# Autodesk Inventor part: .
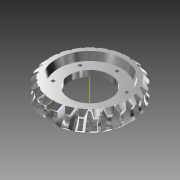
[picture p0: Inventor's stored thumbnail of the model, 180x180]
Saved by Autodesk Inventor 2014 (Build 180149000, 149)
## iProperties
Shininess: 20.0
Length Units: 11269
Angle Units: 11279
Time Units: 11290
Mass Units: 11283
Length Display Precision: 3
Angle Display Precision: 2
Created: 2001-01
Part Number: .
Material: Stainless Steel, 440C
Description: Worm gearing 1/25, 165.
Document SubType Name: Modeling
Density: 7.75 g/cm^3
Appearance: Chrome - Polished
Density: 7.859999999999999
Volumn: 37.595819547659616
Area: 89.95488932430769
PropertySet Name: Model Information
Control State: 0
Master: False
Checked Out: False
ProtocolID: P00020917093351030
Protocol: P00020917093351030<@PID>[Version]<@EL>Version=2.2<@EL>[Main]<@EL>DataFile=SpiData|gear3<@EL>View=MODELB<@EL>Standard=DIN<@EL>PartKey=Gears<@EL>VarLists=A,B,C,D,
Author: PaulN
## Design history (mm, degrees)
sketch "Sketch4"
  geometry: L1 (0, -102.918)-(0, 102.918) reference; L2 (0, 35)-(129.293, 35); L3 (0, 35)-(0, -35); L4 (0, -35)-(129.293, -35); L5 (129.293, 35)-(143.576, 21); L6 (129.293, -35)-(143.576, -21); L7 (-43.64, 0)-(199.773, 0) reference; L8 (107.594, 10)-(70, 10); L9 (107.594, -10)-(70, -10); L10 (107.594, -10)-(114.293, -35); L11 (107.594, 10)-(114.293, 35); L12 (70, 10)-(70, -10); A1 r 30 centre (165, 0) between (143.576, 21) and (143.576, -21); A2 r 73.513 centre (64.646, 0) between (0, 35) and (129.293, 35)
  constraints: 20 end point, 6 point on circle, 5 point on line, 4 perpendicular, 2 centre point, 2 vertical alignment, 1 collinear, 1 equal length, 1 parallel
  dimensions: "d30" = 88.854 deg angle of L6 L5 (= 2 x prf_fi); "d31" = 30 radius of A1 (= prf_a - 0.5 x prf_da2); "d32" = 70 distance of L2.start L3.end (= prf_b2); "d33" = 165 distance from line of L1 A1.centre (= prf_a); "d50" = 44.427 deg angle of L5 L2 (= prf_fi); "d71" = 20 distance between parallel lines of L8 L9; "d74" = 75 deg angle of L2 L11; "d75" = 15 distance of L11.end L2.end; "d76" = 140 diameter of L12 L3
revolve "Revolution3" sketch "Sketch4" stored, may be unused: angle "d35" = 90 deg
workplane "Work Plane4"
sketch "Sketch5"
  geometry: L1 (10, 17.11)-(10, -17.11) reference; L2 (-165.4, 0)-(-92.6, 0) reference; L3 (-155, 12.222)-(-155, -12.222); L4 (-155, -12.222)-(-127, -12.222); L5 (-127, -12.222)-(-103, -3.486); L6 (-103, -3.486)-(-103, 0); L7 (-103, 3.486)-(-127, 12.222); L8 (-127, 12.222)-(-155, 12.222); L9 (-103, 3.486)-(-103, 0); L10 (-115, 0)-(-115, -7.854)
  constraints: 16 end point, 4 perpendicular, 3 equal length, 2 point on line, 1 midpoint, 1 parallel, 1 vertical
  dimensions: "d38" = 165 distance between parallel lines of L1 L3 (= prf_a); "d39" = 20 deg angle of L7 L8 (= prf_alfax); "d40" = 28 distance of L7.end L3.start (= 0.5 x prf_df1); "d41" = 40 distance between parallel lines of L3 L10 (= 0.5 x prf_d1); "d42" = 7.854 distance of L10.start L10.end (= 0.25 x prf_px)
revolve "Revolution4" sketch "Sketch5" stored, may be unused: angle "d43" = 90 deg
workplane "Work Plane5"
workplane "Work Plane6"
workplane "Work Plane7"
workplane "Work Plane13"
sketch "Sketch10"
  geometry: C1 r 70 at (0, 0) reference; C2 r 107.594 at (0, 0) reference; C3 r 5.5 at (0, 92.094)
  constraints: 1 centre point, 1 vertical alignment
  dimensions: "d77" = 11 diameter of C3; "d83" = 10 dimension on C2 C3
extrude "Extrusion1" cut sketch "Sketch10" stored distance "d78" = 10; taper "d79" = 0 deg
pattern_circular "Circular Pattern2" dims angle "d82" = 360 deg
body "Solid1"
pattern_circular "Circular Pattern1" dims angle "d46" = 360 deg
other parameters: "prf_a" = 165 [user parameter; used in 3 equation terms], "prf_fi" = 44.427 deg [user parameter; used in 2 equation terms], "prf_b2" = 70 [user parameter; used in 2 equation terms], "prf_df2" = 226 [user parameter; used in 1 equation term], "hole" = 28.25 (= 0.125 x prf_df2) [user parameter], "prf_gama" = 1.24355 [user parameter; used in 1 equation term], "prf_alfax" = 20 deg [user parameter; used in 1 equation term], "prf_df1" = 56 [user parameter; used in 1 equation term], "prf_px" = 31.416 [user parameter; used in 1 equation term], "d2" = 36.792 (derived), "d4" = 60 deg (derived), "d6" = 30 deg (derived), "d10" = 14 (derived), "d15" = 0, "d17" = 20 deg (derived), "d19" = 9 (derived), "d21" = 13.635 (derived), "d23" = 2.35 (derived), "d25" = 11.5 (derived), "d27" = 0 (derived), "d36" = 7 deg, "d37" = 1.24355 (= prf_gama), "d47" = 0, "d48" = 0, "d49" = 0, "d61" = 35 (= 0.5 x prf_b2)
